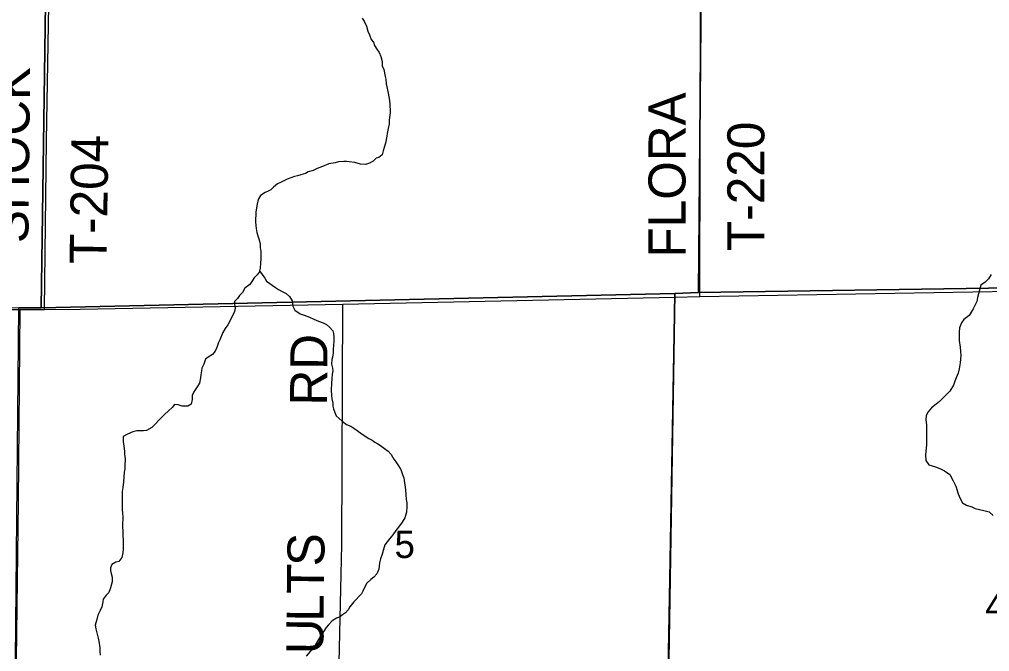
# Model space of a CAD drawing. Extents: x 0 to 34, y 0 to 22.
# Drawn here: x 27.011 to 28.499, y 19.309 to 20.279 of the extents above; entities that cross this region are included whole.
import ezdxf

# ---------------------------------------------------------------- set-up
doc = ezdxf.new("R2010")
doc.units = 0
for name, color, linetype in [('GM_X_County_Road', 7, 'Continuous'), ('GM_X_Minor_River', 7, 'Continuous'), ('GM_X_Section', 7, 'Continuous'), ('GM_X_Section_Text', 7, 'Continuous'), ('GM_X_Township_Road', 7, 'Continuous'), ('GM_X_Township_Road_Text', 7, 'Continuous')]:
    doc.layers.add(name, color=color, linetype=linetype)

msp = doc.modelspace()

# ---------------------------------------------------------------- linework, layer by layer
at = {"layer": 'GM_X_County_Road'}
for p, q in [((28.0544, 19.8539), (28.7306, 19.8653)), ((28.016, 19.8527), (28.0544, 19.8539)), ((27.0117, 19.8339), (27.0492, 19.834))]:
    msp.add_line(p, q, dxfattribs=at)
for points in [[(27.0492, 19.834), (27.1039, 19.8346), (27.5067, 19.8418), (28.016, 19.8527)], [(26.301, 19.8288), (26.5115, 19.8289), (26.8669, 19.8327), (26.9698, 19.8338), (27.0117, 19.8339)]]:
    msp.add_lwpolyline(points, dxfattribs=at)
at = {"layer": 'GM_X_Minor_River'}
for points in [[(27.5366, 20.2809), (27.5396, 20.276), (27.5429, 20.2687), (27.5451, 20.2611), (27.5477, 20.2554), (27.5503, 20.2481), (27.5536, 20.2439), (27.5555, 20.239), (27.5588, 20.2332), (27.5626, 20.2279), (27.5651, 20.2218), (27.567, 20.2142), (27.5673, 20.2077), (27.5698, 20.202), (27.5716, 20.1913), (27.5727, 20.1872), (27.573, 20.1803), (27.5741, 20.1754), (27.5759, 20.1681), (27.5781, 20.1575), (27.5791, 20.1499), (27.5791, 20.1457), (27.5794, 20.14), (27.5793, 20.1358), (27.5785, 20.1283), (27.5777, 20.1241), (27.5776, 20.118), (27.5768, 20.1139), (27.5748, 20.104), (27.5744, 20.0998), (27.572, 20.0888), (27.5704, 20.0824), (27.5688, 20.0771), (27.5672, 20.0714), (27.5622, 20.0669), (27.5581, 20.0662), (27.5531, 20.0613), (27.5477, 20.0584), (27.5413, 20.0565), (27.5337, 20.0566), (27.525, 20.0594), (27.5166, 20.0606), (27.5125, 20.061), (27.5083, 20.0611), (27.5003, 20.0604), (27.495, 20.0589), (27.4855, 20.0571), (27.4756, 20.0534), (27.4676, 20.0501), (27.4611, 20.0471), (27.4535, 20.0449), (27.4493, 20.0423), (27.4421, 20.0405), (27.4371, 20.0391), (27.4326, 20.038), (27.4268, 20.0357), (27.4215, 20.0339), (27.4112, 20.0287), (27.4063, 20.0269), (27.4005, 20.0216), (27.3963, 20.0175), (27.3921, 20.0156), (27.3875, 20.0134), (27.3806, 20.0089), (27.3768, 20.0025), (27.3752, 19.9953), (27.3731, 19.9839), (27.373, 19.968), (27.374, 19.9581), (27.3747, 19.952), (27.3765, 19.9471), (27.3783, 19.941), (27.3798, 19.9341), (27.3801, 19.9288), (27.3812, 19.9227), (27.381, 19.911), (27.3802, 19.9057), (27.3797, 19.8973), (27.3782, 19.8913), (27.3751, 19.8871), (27.3705, 19.8826), (27.3681, 19.8785), (27.3643, 19.8724), (27.3566, 19.8668), (27.3528, 19.86), (27.3482, 19.8551), (27.3451, 19.851), (27.3405, 19.8461), (27.3404, 19.8416), (27.3415, 19.8359), (27.3407, 19.8309), (27.3379, 19.8253), (27.3302, 19.8105), (27.326, 19.8045), (27.3228, 19.7985), (27.3182, 19.7871), (27.3162, 19.783), (27.3147, 19.7788), (27.3131, 19.7743), (27.3108, 19.7698)], [(27.3787, 19.8934), (27.3871, 19.8817), (27.3897, 19.8771), (27.4037, 19.8674), (27.4082, 19.8647), (27.4146, 19.8609), (27.4199, 19.8582), (27.4248, 19.8536), (27.4292, 19.8474), (27.4299, 19.8391), (27.4332, 19.833), (27.4415, 19.8272), (27.4476, 19.8252), (27.4555, 19.8221), (27.4623, 19.819), (27.4695, 19.8159), (27.4767, 19.8135), (27.4819, 19.8108), (27.4864, 19.807), (27.4913, 19.8012), (27.4924, 19.797), (27.4931, 19.7913), (27.493, 19.7837), (27.4926, 19.7796), (27.4921, 19.7727), (27.4921, 19.7678), (27.4912, 19.7629), (27.49, 19.7572), (27.4896, 19.75), (27.491, 19.7439), (27.4914, 19.7397), (27.4905, 19.7348), (27.4897, 19.7276), (27.4892, 19.7208), (27.4891, 19.7105), (27.4894, 19.7018), (27.4901, 19.6968), (27.4912, 19.69), (27.4915, 19.6854), (27.4922, 19.6813), (27.4944, 19.6759), (27.4966, 19.671), (27.5057, 19.6625), (27.5124, 19.6575), (27.5188, 19.6548), (27.5234, 19.6517), (27.529, 19.6482), (27.5365, 19.6428), (27.5467, 19.6359), (27.5516, 19.6332), (27.5557, 19.6305), (27.5606, 19.6278), (27.5648, 19.6251), (27.5708, 19.6208), (27.5761, 19.6166), (27.5809, 19.6116), (27.585, 19.6043), (27.588, 19.6001), (27.591, 19.5955), (27.5959, 19.5883), (27.5984, 19.581), (27.6006, 19.5757), (27.601, 19.5715), (27.602, 19.5647), (27.6031, 19.5571), (27.6034, 19.5495), (27.6041, 19.5426), (27.6048, 19.5373), (27.6051, 19.5309), (27.6046, 19.5229), (27.6018, 19.5142), (27.598, 19.5074), (27.5922, 19.5002), (27.5883, 19.495), (27.5833, 19.4882), (27.5783, 19.4818), (27.5749, 19.4773), (27.571, 19.4728), (27.5686, 19.4644), (27.5671, 19.4584), (27.5647, 19.4512), (27.5631, 19.4451), (27.5627, 19.4402), (27.5619, 19.4357), (27.5591, 19.4285), (27.5545, 19.4232), (27.5495, 19.4195), (27.5438, 19.4142), (27.5395, 19.4063), (27.5376, 19.4018), (27.5353, 19.3976), (27.5237, 19.3856), (27.5176, 19.3777), (27.5149, 19.3732), (27.511, 19.3686), (27.5064, 19.3657), (27.5018, 19.3619), (27.4969, 19.3601), (27.4904, 19.356), (27.4846, 19.3503), (27.4812, 19.3458)], [(28.5013, 19.8876), (28.4975, 19.8811), (28.4921, 19.8759), (28.4856, 19.8714), (28.482, 19.8578), (28.4804, 19.8521), (28.4792, 19.846), (28.4769, 19.8411), (28.4738, 19.8347), (28.4676, 19.8249), (28.4596, 19.8185), (28.4557, 19.8133), (28.4526, 19.8057), (28.4521, 19.7993), (28.4521, 19.7932), (28.4524, 19.7863), (28.4538, 19.7761), (28.4541, 19.7692), (28.4548, 19.7635), (28.4539, 19.7522), (28.4523, 19.7427), (28.451, 19.7363), (28.4479, 19.7291), (28.4456, 19.7238), (28.4436, 19.7177), (28.4378, 19.7087), (28.4321, 19.7027), (28.4267, 19.6974), (28.4221, 19.6925), (28.4171, 19.6884), (28.4099, 19.6832), (28.4045, 19.6768), (28.4018, 19.6711), (28.4013, 19.6647), (28.402, 19.6571), (28.4022, 19.6464), (28.402, 19.6267), (28.4007, 19.6108), (28.401, 19.6024), (28.4058, 19.5955), (28.416, 19.5924)], [(27.3108, 19.7698), (27.3069, 19.7649), (27.3004, 19.7608), (27.2962, 19.7578), (27.2935, 19.7502), (27.2907, 19.7438), (27.2899, 19.7396), (27.2887, 19.7335), (27.2883, 19.729), (27.2867, 19.721), (27.2844, 19.7169), (27.2813, 19.712), (27.2782, 19.7078), (27.2758, 19.7018), (27.2754, 19.6957), (27.2742, 19.6885), (27.2692, 19.6855), (27.2601, 19.6856), (27.2541, 19.6876), (27.2484, 19.688), (27.2449, 19.6835), (27.2392, 19.6783), (27.233, 19.673), (27.2254, 19.6651), (27.2181, 19.6572), (27.2135, 19.6527), (27.2054, 19.6483), (27.2009, 19.6479), (27.1956, 19.6476), (27.1906, 19.6477), (27.1845, 19.6462), (27.1762, 19.6425), (27.17, 19.6388), (27.17, 19.6312), (27.1706, 19.624), (27.1717, 19.6167), (27.172, 19.6118), (27.1727, 19.6046), (27.1722, 19.594), (27.1721, 19.5894), (27.1713, 19.5841), (27.1704, 19.5697), (27.1692, 19.5606), (27.1683, 19.5549), (27.1683, 19.5485), (27.1681, 19.5348), (27.1684, 19.5283), (27.1687, 19.5204), (27.169, 19.5162), (27.169, 19.5113), (27.1685, 19.5059), (27.1685, 19.4999), (27.1692, 19.4945), (27.1695, 19.4896), (27.1694, 19.4854), (27.1698, 19.4813), (27.17, 19.4725), (27.17, 19.4668), (27.1695, 19.4608), (27.1679, 19.4532), (27.1633, 19.4475), (27.1584, 19.4461), (27.1523, 19.4427), (27.1503, 19.4378), (27.1503, 19.4333), (27.1513, 19.4291), (27.1528, 19.423), (27.1531, 19.4161), (27.1503, 19.4067), (27.1476, 19.3999), (27.1438, 19.3954), (27.1391, 19.3897), (27.1387, 19.3856), (27.1371, 19.3776), (27.1344, 19.3719), (27.1309, 19.3648), (27.1293, 19.3583), (27.1269, 19.3496), (27.1276, 19.3439), (27.1312, 19.3298), (27.1323, 19.3249), (27.1341, 19.315), (27.134, 19.3097), (27.1344, 19.3036)], [(28.416, 19.5924), (28.4228, 19.59), (28.43, 19.5865), (28.4379, 19.5808), (28.4431, 19.5708), (28.4472, 19.5628), (28.4508, 19.551), (28.4538, 19.5438), (28.4575, 19.5373), (28.4635, 19.5338), (28.4718, 19.531), (28.4768, 19.5287), (28.49, 19.5255), (28.4983, 19.5235), (28.5047, 19.5178)], [(27.4812, 19.3458), (27.4777, 19.3405), (27.4742, 19.3356), (27.4711, 19.33), (27.4642, 19.3187), (27.4599, 19.3134), (27.4569, 19.3092), (27.4507, 19.3021)]]:
    msp.add_lwpolyline(points, dxfattribs=at)
at = {"layer": 'GM_X_Section'}
for points in [[(29.0645, 20.8822), (29.0488, 19.8748), (29.0105, 19.8743), (28.0523, 19.8602), (28.0611, 20.8611)], [(28.0611, 20.8611), (28.0523, 19.8602), (28.0159, 19.8585), (27.044, 19.8365), (27.0582, 20.8419)], [(27.0582, 20.8419), (27.044, 19.8365), (27.0095, 19.8363), (26.0975, 19.8234), (26.1071, 20.822)], [(29.0105, 19.8743), (29.0034, 18.9139), (28.001, 18.9217), (28.0159, 19.8585), (28.0523, 19.8602)], [(28.0159, 19.8585), (28.001, 18.9217), (27.0012, 18.9192), (27.0095, 19.8363), (27.044, 19.8365)]]:
    msp.add_lwpolyline(points, close=True, dxfattribs=at)
at = {"layer": 'GM_X_Township_Road'}
for p, q in [((28.0544, 19.8539), (28.0568, 20.8556)), ((28.0083, 19.4207), (28.016, 19.8527)), ((28.016, 19.8527), (28.0544, 19.8539)), ((27.0117, 19.8339), (27.0492, 19.834))]:
    msp.add_line(p, q, dxfattribs=at)
for points in [[(27.0492, 19.834), (27.0521, 20.0929), (27.0558, 20.3), (27.0587, 20.5188), (27.0611, 20.719), (27.0623, 20.8364), (27.0625, 20.9)], [(27.504, 19.4276), (27.505, 19.4731), (27.5067, 19.8418)], [(27.0042, 19.0768), (27.005, 19.173), (27.0061, 19.2969), (27.0091, 19.5392), (27.0117, 19.8339)], [(27.4952, 18.8928), (27.4954, 18.9016), (27.4964, 18.961), (27.5002, 19.2468), (27.504, 19.4276)], [(27.9971, 18.7155), (27.9972, 18.7243), (27.9997, 18.9437), (28.0083, 19.4207)]]:
    msp.add_lwpolyline(points, dxfattribs=at)

# ---------------------------------------------------------------- texts
at = {"layer": 'GM_X_Section_Text'}
for s, p in [('5', (27.5861, 19.4526)), ('4', (28.4924, 19.3582))]:
    msp.add_text(s, height=0.0419, rotation=0, dxfattribs=at).set_placement(p)
at = {"layer": 'GM_X_Township_Road_Text'}
for s, height, rotation, p in [('SHOCK', 0.05682, 89.39, (27.0242, 19.9355)), ('FLORA', 0.05682, 90, (28.0325, 19.9136)), ('T-220', 0.05682, 90, (28.1535, 19.9236)), ('T-204', 0.05682, 89.1569, (27.1443, 19.903)), ('RD', 0.05682, 89.5063, (27.4825, 19.6863)), ('S', 0.0568, 88.6124, (27.478, 19.4395)), ('T', 0.0568, 89.4, (27.4776, 19.3972)), ('L', 0.0568, 89.4257, (27.4771, 19.3547)), ('U', 0.0568, 89.4244, (27.4766, 19.3047))]:
    msp.add_text(s, height=height, rotation=rotation, dxfattribs=at).set_placement(p)

doc.saveas('drawing.dxf')
